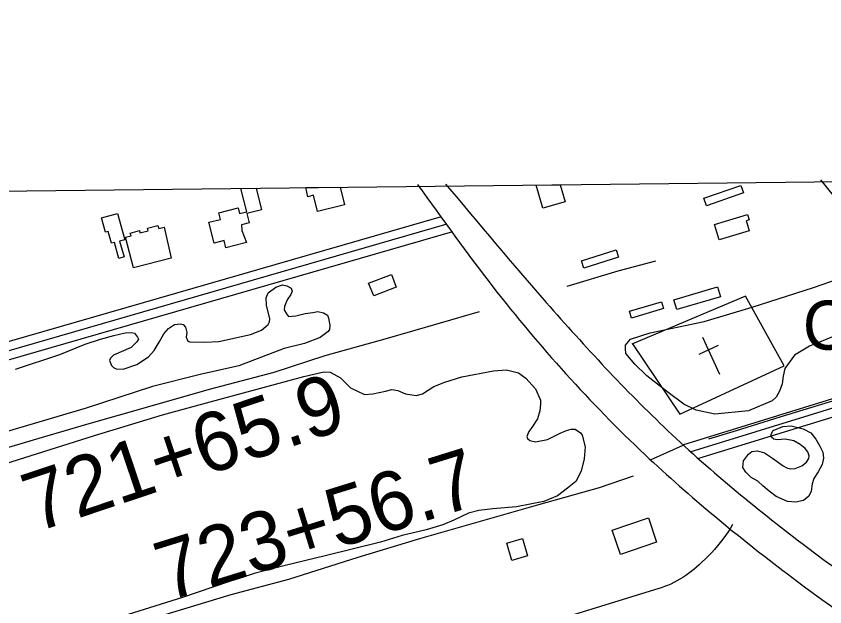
# Model space of a CAD drawing. Extents: x 3684037 to 3722149, y 433263 to 459021.
# Drawn here: x 3694344 to 3695714, y 456228 to 457228 of the extents above; entities that cross this region are included whole.
import ezdxf

# ---------------------------------------------------------------- set-up
doc = ezdxf.new("R2010")
doc.units = 0
for name, color, linetype in [('V-BLDG-OTLN', 7, 'Continuous'), ('V-GRID-FRAM', 7, 'Continuous'), ('V-ROAD-CNTR', 7, 'Continuous'), ('V-SITE-OTLN', 7, 'Continuous'), ('V-SITE-OTLN-IDEN', 7, 'Continuous'), ('V-SITE-VEGE', 7, 'Continuous'), ('V-SURV-IDEN', 7, 'Continuous'), ('V-TOPO-SHOR', 7, 'Continuous')]:
    doc.layers.add(name, color=color, linetype=linetype)

msp = doc.modelspace()

# ---------------------------------------------------------------- linework, layer by layer
at = {"layer": 'V-BLDG-OTLN'}
for p, q in [((3694834.9, 456937.7), (3694893.3, 456938.4)), ((3694838.7, 456922.4), (3694834.9, 456937.7)), ((3694893.3, 456938.4), (3694900.8, 456908.6)), ((3695225.1, 456942.2), (3695265.9, 456942.7)), ((3695236.5, 456902.7), (3695225.1, 456942.2)), ((3695265.9, 456942.7), (3695274.3, 456913.6)), ((3694725, 456936.4), (3694750.9, 456936.7)), ((3694735.1, 456897), (3694725, 456936.4)), ((3694750.9, 456936.7), (3694760.1, 456900.4)), ((3694848.1, 456924.8), (3694838.7, 456922.4)), ((3694855.1, 456897.1), (3694848.1, 456924.8)), ((3695274.3, 456913.6), (3695236.5, 456902.7)), ((3694687.7, 456895), (3694720.5, 456903.3)), ((3694720.5, 456903.3), (3694722.9, 456893.9)), ((3694722.9, 456893.9), (3694735.1, 456897)), ((3694760.1, 456900.4), (3694735.1, 456894)), ((3694900.8, 456908.6), (3694855.1, 456897.1)), ((3694670.9, 456879), (3694690.5, 456884)), ((3694690.5, 456884), (3694687.7, 456895)), ((3694735.1, 456894), (3694739.1, 456878.1)), ((3694679.9, 456843.8), (3694670.9, 456879)), ((3694739.1, 456878.1), (3694726.3, 456874.8)), ((3694726.3, 456874.8), (3694726.6, 456865)), ((3694726.6, 456865), (3694734.5, 456844.6)), ((3694696.5, 456848), (3694679.9, 456843.8)), ((3694699.6, 456835.8), (3694696.5, 456848)), ((3694734.5, 456844.6), (3694699.6, 456835.8))]:
    msp.add_line(p, q, dxfattribs=at)
for points in [[(3695576.5, 456928.8), (3695513.8, 456907.1), (3695509.4, 456919.7), (3695572.1, 456941.4)], [(3694488.7, 456886.5), (3694515.9, 456894.2), (3694528.6, 456849.4), (3694519.7, 456846.9), (3694527.2, 456820.3), (3694518.5, 456817.8), (3694510.8, 456845.1), (3694506.1, 456843.8), (3694500.5, 456863.7), (3694495.5, 456862.3)], [(3695586, 456864.8), (3695535.5, 456849.5), (3695527.7, 456875.2), (3695583.4, 456892.1), (3695586.2, 456883.1), (3695581.2, 456881.6), (3695582.8, 456876.3), (3695582.6, 456876.2)], [(3694606.8, 456818.3), (3694543.1, 456802), (3694529.8, 456853.6), (3694539, 456855.9), (3694537.7, 456860.9), (3694553.1, 456864.9), (3694554.1, 456861), (3694568.2, 456864.6), (3694567.1, 456869.1), (3694584.6, 456873.6), (3694585.9, 456868.6), (3694594.9, 456870.9)], [(3695364.7, 456819.9), (3695306.2, 456801.3), (3695302.2, 456813.7), (3695360.8, 456832.3)], [(3694941.4, 456776.2), (3694980.2, 456790.5), (3694988.2, 456769.2), (3694950.4, 456754.6)], [(3695458.8, 456747.8), (3695532.7, 456769.6), (3695537.6, 456753), (3695463.7, 456731.2)], [(3695383.4, 456728.4), (3695437.9, 456744.2), (3695441.2, 456732.8), (3695386.7, 456716.9)], [(3695354.1, 456357.7), (3695415.4, 456378.3), (3695429.2, 456337.1), (3695368, 456316.5)], [(3695202.1, 456343.3), (3695210.4, 456314.2), (3695183.9, 456306.6), (3695175.6, 456335.7)]]:
    msp.add_lwpolyline(points, close=True, dxfattribs=at)
at = {"layer": 'V-GRID-FRAM'}
msp.add_lwpolyline([(3688058.9, 456858.9), (3719789.3, 457228.1), (3720008.8, 439046.9), (3688262.6, 438677.5), (3688058.9, 456858.9)], dxfattribs=at)
at = {"layer": 'V-ROAD-CNTR'}
for points in [[(3695707.1, 456951.1), (3695873.9, 456744.5), (3695953.6, 456668.6)], [(3695064.5, 456888.5), (3693713.7, 456498.8)], [(3695074, 456875.7), (3693717.9, 456484.4)], [(3695083.5, 456862.8), (3693722, 456470)], [(3695473.5, 456502.3), (3695925.7, 456641.4), (3695953.6, 456668.6)], [(3695486.3, 456490.6), (3695933.6, 456628.1), (3695967.1, 456660.8)], [(3695499.2, 456478.9), (3695941.4, 456614.9), (3695975.4, 456647.9)], [(3695419.1, 456476.7), (3695474.5, 456501.4)], [(3695558.2, 456367.4), (3695554.3, 456361), (3695550.3, 456354.8), (3695546.1, 456348.6), (3695541.8, 456342.6), (3695537.2, 456336.7), (3695532.5, 456330.9), (3695527.7, 456325.2), (3695522.7, 456319.7), (3695517.5, 456314.3), (3695512.2, 456309.1), (3695506.7, 456304.1), (3695501.2, 456299.2), (3695496.9, 456295.2), (3695492.5, 456291.3), (3695488, 456287.7), (3695483.4, 456284.1), (3695478.6, 456280.8), (3695473.7, 456277.6), (3695468.8, 456274.6), (3695463.7, 456271.7), (3695458.5, 456269), (3695453.2, 456266.5), (3695447.9, 456264.2), (3695442.5, 456262.1), (3695437, 456260.1), (3695431.4, 456258.3), (3695425.8, 456256.8), (3695334.2, 456228.7), (3695242.9, 456200.2)]]:
    msp.add_lwpolyline(points, dxfattribs=at)
for points in [[(3695024.3, 456943.2), (3695152.1, 456769.7), (3695409.8, 456485.5), (3695651.2, 456283.5), (3695889.4, 456120.4), (3696136.9, 455985.7), (3696236.4, 455936), (3696394, 455863.1), (3696621.9, 455754.9), (3696886.1, 455629.6), (3697071.3, 455542.4), (3697240.7, 455456.7), (3697428.9, 455333.1), (3697699.2, 455127.1), (3697849.7, 454985.5), (3697955.2, 454875.4)], [(3695071.9, 456943.7), (3695242.5, 456743.3), (3695448.6, 456526), (3695685.1, 456328.2), (3695918.7, 456168.2), (3696162.8, 456035.3), (3696260.6, 455986.4), (3696417.7, 455913.7), (3696645.9, 455805.4), (3696910, 455680.2), (3697095.9, 455592.7), (3697268.8, 455505.2), (3697461.2, 455378.7), (3697735.5, 455169.8), (3697889, 455025.2), (3697995.6, 454914.1)]]:
    msp.add_spline(points, degree=3, dxfattribs=at)
at = {"layer": 'V-SITE-OTLN'}
for p, q in [((3695536.6, 456621.2), (3695507.6, 456683.7)), ((3695533.4, 456670.4), (3695501.1, 456655.4))]:
    msp.add_line(p, q, dxfattribs=at)
msp.add_lwpolyline([(3695388.7, 456673), (3695468.6, 456553.9), (3695645.7, 456635.9), (3695580.1, 456754), (3695387.6, 456672.9)], dxfattribs=at)
at = {"layer": 'V-SITE-VEGE'}
for points in [[(3695744.1, 456691.6), (3695688.2, 456669.5), (3695663, 456654.3), (3695646.8, 456631.6), (3695644, 456618.6), (3695641.8, 456605.6), (3695637.8, 456593.1), (3695632.1, 456582.9), (3695625.1, 456576.9), (3695585.1, 456559.8), (3695527.8, 456554.2), (3695496.4, 456560.9), (3695475.5, 456571.2), (3695449.2, 456590.9), (3695412.8, 456618.8), (3695392.4, 456638.6), (3695377.3, 456656.7), (3695376.6, 456665), (3695376.5, 456670.9), (3695385.3, 456681.1), (3695418.2, 456691.6), (3695510.2, 456711.3), (3695591.4, 456735.5), (3695695, 456768.9), (3695737.4, 456783.2)], [(3694551.4, 456681.1), (3694549, 456676.9), (3694539.1, 456667.3), (3694509, 456653.8), (3694504.4, 456649), (3694502.6, 456644.8), (3694505.7, 456636.6), (3694509.3, 456633.1), (3694513.5, 456630.7), (3694525.4, 456630.3), (3694549, 456638.4), (3694568.4, 456651.1), (3694578.3, 456661.9), (3694586.4, 456676.3), (3694594.5, 456690.1), (3694602.7, 456699.1), (3694612.7, 456705.7), (3694622.8, 456707.1), (3694627.5, 456706), (3694631.2, 456701.3), (3694633.7, 456692.4), (3694632.6, 456684.7), (3694635.1, 456677.6), (3694638.6, 456676.5), (3694663.6, 456676.2), (3694687.9, 456677.2), (3694741.1, 456689.2), (3694760, 456696.6), (3694767.6, 456702.6), (3694771.1, 456706.2), (3694773.4, 456710.4), (3694773.9, 456715.8), (3694768.3, 456738.8), (3694768.1, 456751.3), (3694771.5, 456759.6), (3694784.4, 456769.3), (3694795.6, 456773), (3694802.8, 456771.4), (3694810, 456767.3), (3694811.8, 456762.6), (3694809.5, 456756.6), (3694803.7, 456747.7), (3694799.1, 456736.3), (3694798.6, 456731), (3694802.3, 456723.9), (3694805.9, 456719.8), (3694818.4, 456720.6), (3694833.7, 456724.4), (3694846.7, 456726.3), (3694855.6, 456728.2), (3694865.1, 456726), (3694871.7, 456721.9), (3694873.6, 456716.6), (3694875.5, 456704.8), (3694875, 456697.7), (3694872.7, 456694.1), (3694859.2, 456683.8), (3694832.7, 456673.9), (3694798.4, 456665.1), (3694721.7, 456636.1), (3694656, 456621.5), (3694575.1, 456600.8), (3694462.9, 456564.2), (3694323.5, 456523.1)], [(3694343.3, 456630.2), (3694418.2, 456654.9), (3694461.3, 456672.7), (3694487.3, 456681.4), (3694509.7, 456687.1), (3694529.2, 456692.1), (3694539.9, 456692.2), (3694544.7, 456691.1), (3694550.1, 456684.7), (3694551.4, 456681.1)], [(3694325.3, 456470.1), (3694477.2, 456518.1), (3694592.4, 456553), (3694666.8, 456573.6), (3694756.6, 456597.5), (3694831.7, 456618.1), (3694865.4, 456625.7), (3694876.1, 456625.3), (3694894, 456615.5), (3694910.9, 456598.5), (3694934.2, 456587.6), (3694948.4, 456588.4), (3694970.3, 456592.8), (3694980.9, 456596), (3694991, 456594.3), (3695004.2, 456588.6), (3695022, 456585.9), (3695032.7, 456588.4), (3695052, 456601.1), (3695070.3, 456608.5), (3695099.3, 456617.2), (3695153.1, 456627.5), (3695175, 456629), (3695195.3, 456624), (3695207.9, 456615.3), (3695224.2, 456597.1), (3695232.7, 456577.6), (3695232.8, 456571.7), (3695231.8, 456559.8), (3695227.3, 456546.1), (3695218, 456531.7), (3695212.7, 456524.5), (3695209.3, 456516.2), (3695210.5, 456513.2), (3695214.7, 456509.7), (3695224.3, 456507.5), (3695244.4, 456511.4), (3695266.2, 456521.8), (3695276.8, 456526.7), (3695284.5, 456528.6), (3695291.6, 456528.7), (3695300.6, 456522.3), (3695303, 456518.7), (3695308.6, 456498.6), (3695306.6, 456478.4), (3695301.5, 456457.6), (3695292.3, 456440.3), (3695278.2, 456428.8), (3695261.2, 456416.1), (3695238.2, 456406.3), (3695192, 456397.3), (3695151.7, 456393.7), (3695128, 456391), (3695110.9, 456386.6), (3695085.6, 456374.4), (3695067.3, 456367), (3695038.9, 456358.3), (3694998.1, 456348.8), (3694961.5, 456337.6), (3694868.1, 456314.3), (3694800.1, 456297.9), (3694747.5, 456284.1), (3694703.8, 456270.4), (3694625.9, 456243.8)], [(3694625.9, 456243.8), (3694460.1, 456191.7), (3694344, 456152.2)]]:
    msp.add_lwpolyline(points, dxfattribs=at)
msp.add_lwpolyline([(3695625.8, 456479.5), (3695643.7, 456466.7), (3695649.7, 456463.2), (3695655.6, 456461.5), (3695663.9, 456462.3), (3695675.1, 456466.6), (3695683.3, 456472.6), (3695687.3, 456479.2), (3695687.9, 456483.3), (3695685.4, 456490.4), (3695681.2, 456496.2), (3695672.8, 456502.6), (3695662.1, 456509), (3695647.2, 456511.7), (3695633.6, 456510.9), (3695627.7, 456512), (3695624.1, 456514.9), (3695623.4, 456520.2), (3695626.9, 456526.2), (3695643.4, 456533), (3695657.5, 456534.3), (3695677.7, 456529.3), (3695690.8, 456522.4), (3695699.3, 456511.9), (3695706, 456500.1), (3695710.8, 456489.6), (3695712.2, 456479.5), (3695710, 456468.8), (3695703, 456456.3), (3695695.5, 456445), (3695692.7, 456436), (3695691.1, 456423.6), (3695687.1, 456415.3), (3695678.3, 456408), (3695665.3, 456404.9), (3695651.1, 456406.5), (3695632.1, 456414.5), (3695620.1, 456423.8), (3695609.3, 456432.5), (3695600.9, 456440.6), (3695589.6, 456447), (3695580.6, 456455.7), (3695575.7, 456463.9), (3695576.8, 456475.2), (3695584.9, 456486.6), (3695590.7, 456490.8), (3695600.2, 456492.1), (3695612.1, 456488.7)], close=True, dxfattribs=at)
at = {"layer": 'V-TOPO-SHOR'}
for points in [[(3695427.3, 456813.2), (3695363.9, 456796.3), (3695277.1, 456770.3)], [(3695128.6, 456727.7), (3695062.5, 456708.2), (3694969.2, 456680.9), (3694867.5, 456652.9), (3694780.6, 456624.5), (3694671.3, 456595.8), (3694570.9, 456567.2), (3694463.4, 456536.8), (3694372.9, 456510.1), (3694253.1, 456474.8), (3694150.3, 456446.1), (3694051.6, 456417.6), (3693955.8, 456391.4), (3693763.2, 456327.6)], [(3695932.4, 456635.8), (3695870.2, 456616.6), (3695760.9, 456586.2), (3695638.2, 456549), (3695564.2, 456526.1), (3695517, 456511.8)], [(3695389.8, 456448.9), (3695332, 456429.6), (3695229.2, 456400.4), (3695146.4, 456376.8), (3695027.7, 456343.2), (3694923.2, 456311.6), (3694805.7, 456273.9), (3694708.2, 456248.3), (3694590.7, 456212.4), (3694486.8, 456182), (3694384, 456148.7), (3694271.3, 456114), (3694187.9, 456089.8), (3694079.2, 456057), (3694030.7, 456036.8)]]:
    msp.add_lwpolyline(points, dxfattribs=at)

# ---------------------------------------------------------------- texts
at = {"layer": 'V-SITE-OTLN-IDEN'}
msp.add_text('Cem.', height=83, dxfattribs=at).set_placement((3695677, 456663.4))
at = {"layer": 'V-SURV-IDEN'}
for s, rotation, p in [('721+65.9', 18.5238, (3694376.9, 456353.3)), ('723+56.7', 17.2339, (3694599.6, 456237))]:
    msp.add_text(s, height=100, rotation=rotation, dxfattribs=at).set_placement(p)

doc.saveas('drawing.dxf')
